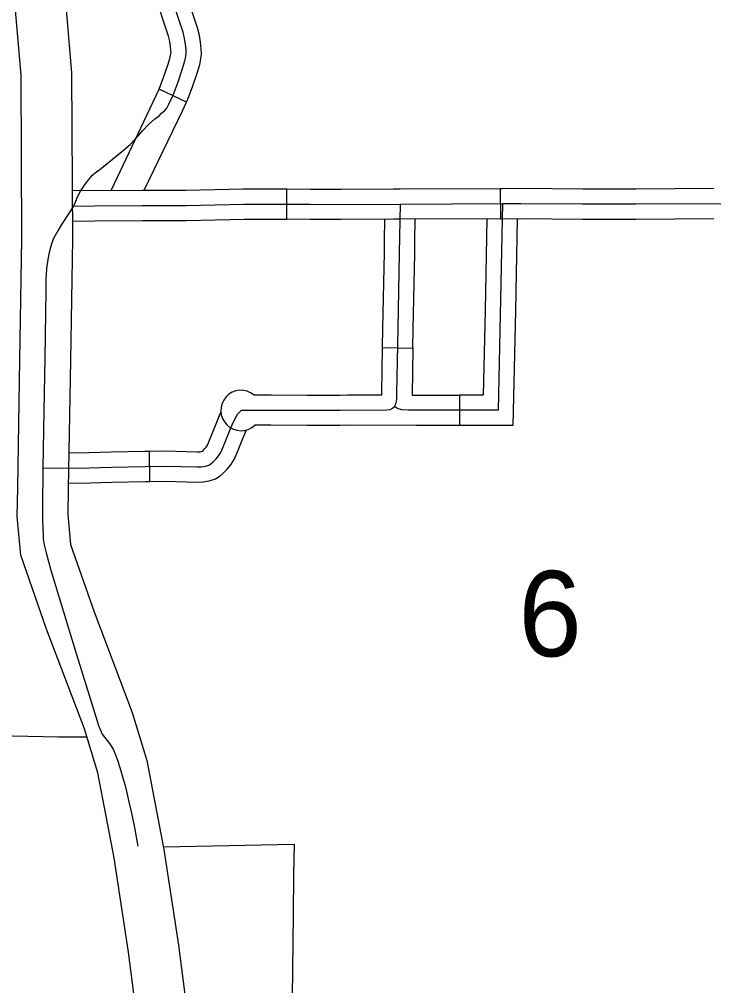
# Model space of a CAD drawing. Extents: x 670147 to 673275, y 705573 to 707613.
# Drawn here: x 671930 to 671998.7, y 706329.9 to 706425.4 of the extents above; entities that cross this region are included whole.
import ezdxf

# ---------------------------------------------------------------- set-up
doc = ezdxf.new("R2010")
doc.units = 0
for name, color, linetype in [('10', 7, 'Continuous'), ('31', 7, 'Continuous'), ('32', 7, 'Continuous'), ('33', 7, 'Continuous'), ('5', 7, 'Continuous'), ('6', 7, 'Continuous')]:
    doc.layers.add(name, color=color, linetype=linetype)

msp = doc.modelspace()

# ---------------------------------------------------------------- linework, layer by layer
at = {"layer": '10'}
for points in [[(671925.161, 706488.788), (671930.161, 706488.802), (671930.168, 706486.139), (671930.29, 706467.257), (671930.533, 706459.613), (671930.907, 706454.573), (671931.657, 706447.956), (671933.489, 706436.01), (671934.218, 706430.741), (671935.131, 706420.145), (671935.217, 706403.691), (671935.015, 706391.709), (671934.802, 706379.032), (671934.759, 706376.461), (671935.028, 706373.491), (671937.35, 706366.833), (671941.135, 706356.873), (671942.586, 706352.115), (671944.273, 706343.331), (671945.713, 706333.857), (671947.062, 706323.357), (671947.64, 706307.924), (671948.188, 706298.414)], [(671948.188, 706298.414), (671943.196, 706298.126), (671942.646, 706307.687), (671942.074, 706322.944), (671940.761, 706333.162), (671939.344, 706342.484), (671937.726, 706350.911), (671936.401, 706355.254), (671932.651, 706365.121), (671930.104, 706372.426), (671929.755, 706376.277), (671929.803, 706379.116), (671930.016, 706391.793), (671930.216, 706403.72), (671930.132, 706419.917), (671929.247, 706430.184), (671928.541, 706435.289), (671926.7, 706447.295), (671925.928, 706454.106), (671925.539, 706459.348), (671925.291, 706467.161), (671925.168, 706486.116), (671925.161, 706488.788)]]:
    msp.add_lwpolyline(points, dxfattribs=at)
at = {"layer": '31'}
for p, q in [((671956.421, 706405.668), (671956.434, 706408.668)), ((671977.542, 706408.714), (671977.553, 706405.714)), ((671965.899, 706392.969), (671968.898, 706392.917)), ((671973.502, 706388.28), (671973.502, 706385.28))]:
    msp.add_line(p, q, dxfattribs=at)
for points in [[(671937.774, 706410.473), (671937.298, 706410.105), (671937.039, 706409.853), (671936.808, 706409.608), (671936.448, 706409.154), (671936.246, 706408.858), (671936.023, 706408.469), (671935.691, 706407.871), (671935.511, 706407.416), (671935.31, 706406.98), (671934.144, 706405.153), (671933.769, 706404.514), (671933.499, 706404.076), (671933.336, 706403.768), (671933.182, 706403.334), (671933.037, 706402.872), (671932.922, 706402.371), (671932.816, 706401.89), (671932.739, 706401.475), (671932.671, 706401.023), (671932.642, 706400.729), (671932.585, 706399.748), (671932.58, 706398.62), (671932.474, 706391.942), (671932.387, 706386.708), (671932.297, 706381.039), (671932.262, 706377.157), (671932.262, 706375.953), (671932.272, 706375.028), (671932.311, 706374.518), (671932.33, 706374.065), (671932.426, 706373.477), (671932.609, 706372.668), (671933.086, 706370.949), (671934.318, 706366.824), (671935.618, 706362.605), (671936.99, 706358.151), (671937.779, 706355.604), (671937.952, 706355.192), (671938.144, 706354.728), (671938.385, 706354.42), (671938.635, 706354.102), (671938.895, 706353.803), (671939.232, 706353.254), (671939.55, 706352.512), (671939.752, 706351.96), (671940.003, 706351.122), (671940.224, 706350.276), (671940.349, 706349.881), (671940.59, 706348.928), (671940.802, 706348.042), (671941.052, 706346.934), (671941.312, 706345.663), (671941.684, 706343.652)], [(671935.192, 706408.5), (671942.148, 706408.542), (671945.869, 706408.542)], [(671945.869, 706408.542), (671946.449, 706408.542), (671952.155, 706408.672), (671955.447, 706408.672), (671956.434, 706408.668)], [(671956.434, 706408.668), (671958.755, 706408.658), (671961.773, 706408.643), (671966.978, 706408.675)], [(671966.978, 706408.675), (671967.655, 706408.679), (671977.542, 706408.714)], [(671977.542, 706408.714), (671977.75, 706408.715), (671979.588, 706408.73), (671985.696, 706408.686), (671988.107, 706408.686)], [(671988.107, 706408.686), (671990.946, 706408.686), (671998.657, 706408.736)], [(671935.31, 706406.98), (671937.368, 706407.013), (671942.153, 706407.042), (671946.466, 706407.042), (671952.172, 706407.172), (671955.443, 706407.172), (671958.748, 706407.158), (671961.774, 706407.143), (671967.662, 706407.179), (671977.758, 706407.215), (671979.588, 706407.23), (671985.691, 706407.186), (671990.951, 706407.186), (671999.93, 706407.244)], [(671951.897, 706386.755), (671951.99, 706386.789), (671952.306, 706386.798), (671954.863, 706386.789), (671958.394, 706386.781), (671961.692, 706386.781), (671966.324, 706386.815), (671966.648, 706386.849), (671966.895, 706386.986), (671967.082, 706387.156), (671967.21, 706387.424), (671967.261, 706387.668), (671967.296, 706387.864), (671967.321, 706388.447), (671967.432, 706394.864), (671967.577, 706402.309), (671967.662, 706407.179)], [(671977.758, 706407.215), (671977.328, 706386.78)], [(671935.207, 706405.478), (671937.385, 706405.514), (671942.157, 706405.542), (671945.869, 706405.542)], [(671945.869, 706405.542), (671946.483, 706405.542), (671952.189, 706405.672), (671955.44, 706405.672), (671956.421, 706405.668)], [(671966.997, 706405.675), (671961.775, 706405.643), (671958.741, 706405.658), (671956.421, 706405.668)], [(671966.098, 706403.527), (671966.135, 706405.67)], [(671977.553, 706405.714), (671967.669, 706405.679), (671966.997, 706405.675)], [(671969.097, 706403.475), (671969.136, 706405.684)], [(671976.226, 706405.71), (671976.036, 706396.689)], [(671977.553, 706405.714), (671977.767, 706405.715), (671979.589, 706405.73), (671985.686, 706405.686), (671988.107, 706405.686)], [(671979.227, 706405.732), (671979.036, 706396.626)], [(671988.107, 706405.686), (671990.956, 706405.686), (671998.677, 706405.736)], [(671965.899, 706392.969), (671965.932, 706394.891), (671966.077, 706402.336), (671966.098, 706403.527)], [(671968.898, 706392.917), (671968.932, 706394.836), (671969.077, 706402.281), (671969.097, 706403.475)], [(671976.036, 706396.689), (671975.859, 706388.28), (671973.502, 706388.28)], [(671979.036, 706396.626), (671978.797, 706385.28), (671973.502, 706385.28)], [(671962.439, 706388.287), (671965.814, 706388.311), (671965.822, 706388.493), (671965.899, 706392.969)], [(671968.898, 706392.917), (671968.818, 706388.28)], [(671953.173, 706388.295), (671954.867, 706388.289), (671958.396, 706388.281), (671961.687, 706388.281), (671962.439, 706388.287)], [(671968.818, 706388.28), (671973.502, 706388.28)], [(671977.328, 706386.78), (671968.47, 706386.78), (671967.805, 706386.831), (671967.379, 706386.951), (671967.082, 706387.156)], [(671962.461, 706385.287), (671961.698, 706385.281), (671958.392, 706385.281), (671954.858, 706385.289), (671953.263, 706385.295)], [(671969.249, 706385.28), (671962.461, 706385.287)], [(671973.502, 706385.28), (671969.249, 706385.28)]]:
    msp.add_lwpolyline(points, dxfattribs=at)
msp.add_arc((671951.897, 706386.755), 2, 50.34202, 313.08949, dxfattribs=at)
at = {"layer": '32'}
for p, q in [((671946.507, 706417.239), (671943.798, 706418.529)), ((671942.88, 706379.735), (671942.829, 706382.734))]:
    msp.add_line(p, q, dxfattribs=at)
for points in [[(671946.507, 706417.24), (671946.569, 706417.371), (671947.099, 706418.775), (671947.549, 706420.119), (671947.803, 706420.987), (671947.872, 706421.309), (671947.926, 706421.622), (671947.972, 706421.989), (671947.962, 706422.522), (671947.893, 706423.194), (671947.782, 706423.852), (671947.594, 706424.61), (671947.161, 706425.887), (671946.629, 706427.579), (671946.368, 706428.443)], [(671937.774, 706410.473), (671939.193, 706411.602), (671940.267, 706412.489), (671940.937, 706413.065), (671941.448, 706413.613), (671942.191, 706414.463), (671942.767, 706415.062), (671943.343, 706415.566), (671943.783, 706415.905), (671944.042, 706416.15), (671944.309, 706416.409), (671944.547, 706416.669), (671944.655, 706416.842), (671944.756, 706417.051), (671945.188, 706417.959), (671945.685, 706419.278), (671946.117, 706420.568), (671946.348, 706421.354), (671946.398, 706421.592), (671946.442, 706421.844), (671946.47, 706422.07), (671946.463, 706422.43), (671946.406, 706422.992), (671946.312, 706423.547), (671946.153, 706424.189), (671945.736, 706425.421), (671945.195, 706427.137)], [(671943.798, 706418.529), (671943.806, 706418.547), (671944.272, 706419.781), (671944.686, 706421.018), (671944.893, 706421.721), (671944.925, 706421.874), (671944.958, 706422.066), (671944.969, 706422.15), (671944.965, 706422.338), (671944.918, 706422.791), (671944.842, 706423.242), (671944.712, 706423.767), (671944.31, 706424.955), (671943.762, 706426.694), (671943.496, 706427.577)], [(671939.035, 706408.523), (671943.798, 706418.529)], [(671942.316, 706408.543), (671946.108, 706416.403), (671946.507, 706417.239)], [(671932.297, 706381.039), (671936.916, 706381.082), (671939.085, 706381.159), (671942.417, 706381.227), (671944.403, 706381.261), (671947.558, 706381.167), (671947.993, 706381.184), (671948.394, 706381.253), (671948.709, 706381.355), (671948.914, 706381.491), (671949.144, 706381.687), (671949.433, 706381.96), (671949.672, 706382.259), (671949.902, 706382.608), (671950.166, 706383.231), (671950.695, 706384.556), (671951.087, 706385.511), (671951.436, 706386.193), (671951.573, 706386.414), (671951.897, 706386.755)], [(671942.829, 706382.734), (671944.412, 706382.762), (671947.551, 706382.668), (671947.837, 706382.679), (671948.034, 706382.713), (671948.035, 706382.713), (671948.142, 706382.805), (671948.328, 706382.98), (671948.457, 706383.141), (671948.575, 706383.32), (671948.779, 706383.802), (671949.304, 706385.118), (671949.904, 706386.58)], [(671942.88, 706379.735), (671944.394, 706379.761), (671947.565, 706379.667), (671948.149, 706379.689), (671948.753, 706379.792), (671949.369, 706379.992), (671949.819, 706380.292), (671950.145, 706380.57), (671950.539, 706380.941), (671950.887, 706381.376), (671951.23, 706381.897), (671951.554, 706382.66), (671952.085, 706383.993), (671952.428, 706384.827)], [(671934.862, 706382.563), (671936.883, 706382.582), (671939.043, 706382.658), (671942.389, 706382.727), (671942.829, 706382.734)], [(671934.811, 706379.563), (671936.95, 706379.582), (671939.126, 706379.659), (671942.445, 706379.727), (671942.88, 706379.735)]]:
    msp.add_lwpolyline(points, dxfattribs=at)
at = {"layer": '33'}
msp.add_lwpolyline([(671936.647, 706354.428), (671933.84, 706354.442), (671923.228, 706354.664)], dxfattribs=at)
at = {"layer": '6'}
msp.add_lwpolyline([(671944.233, 706343.593), (671957.14, 706343.862), (671957.102, 706340.859), (671957.058, 706336.857), (671956.959, 706328.714)], dxfattribs=at)

# ---------------------------------------------------------------- texts
at = {"layer": '5'}
msp.add_text('6', height=8.448, dxfattribs=at).set_placement((671979.333, 706362.434))

doc.saveas('drawing.dxf')
